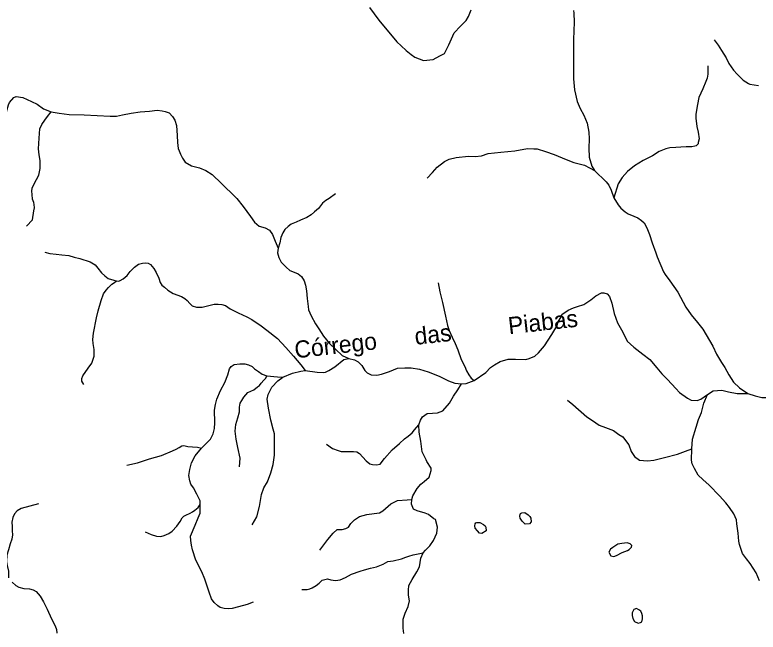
# Model space of a CAD drawing. Extents: x 436.3 to 500.4, y 8231 to 8286.4.
# Drawn here: x 456.96 to 465.65, y 8250.52 to 8257.73 of the extents above; entities that cross this region are included whole.
import ezdxf
from ezdxf.enums import TextEntityAlignment as Align

# ---------------------------------------------------------------- set-up
doc = ezdxf.new("R2010")
doc.units = 0
doc.header["$LTSCALE"] = 0.08
doc.linetypes.add('LONG_DASHED', pattern=[7.5, 6, -1.5])
doc.layers.add('2', color=7, linetype='Continuous', lineweight=25)
doc.layers.add('9', color=7, linetype='LONG_DASHED', lineweight=25)
doc.layers.add('61', color=7, linetype='Continuous')

msp = doc.modelspace()

# ---------------------------------------------------------------- linework, layer by layer
at = {"layer": '2'}
for points in [[(462.8867, 8251.9127), (462.9218, 8251.9161), (462.9637, 8251.8899), (462.9819, 8251.8722), (462.9921, 8251.85), (462.9971, 8251.809), (462.9762, 8251.7844), (462.9269, 8251.7827), (462.8929, 8251.8152), (462.868, 8251.8529), (462.8629, 8251.8745), (462.8668, 8251.8956), (462.8736, 8251.907)], [(462.3636, 8251.8014), (462.3965, 8251.8006), (462.4406, 8251.7786), (462.4588, 8251.7609), (462.4678, 8251.7447), (462.472, 8251.7027), (462.422, 8251.6708), (462.3933, 8251.6778), (462.3698, 8251.7039), (462.3443, 8251.7347), (462.3398, 8251.7632), (462.3437, 8251.7843), (462.3505, 8251.7957)], [(463.9519, 8251.5108), (463.9244, 8251.4907), (463.9045, 8251.4526), (463.927, 8251.4103), (463.962, 8251.4053), (463.9957, 8251.4153), (464.0621, 8251.4506), (464.1221, 8251.4756), (464.1411, 8251.4856), (464.1682, 8251.511), (464.1718, 8251.5339), (464.1555, 8251.5525), (464.1185, 8251.5635), (464.057, 8251.5561), (464.0119, 8251.546)], [(464.2292, 8250.7975), (464.1971, 8250.7855), (464.1771, 8250.7452), (464.1771, 8250.7129), (464.1852, 8250.6807), (464.2053, 8250.6445), (464.2495, 8250.6244), (464.2736, 8250.6324), (464.2896, 8250.6405), (464.2976, 8250.6767), (464.2976, 8250.7089), (464.2894, 8250.7371), (464.2774, 8250.7653), (464.2573, 8250.7815)]]:
    msp.add_lwpolyline(points, close=True, dxfattribs=at)
at = {"layer": '9'}
for points in [[(461.109, 8257.8183), (461.2167, 8257.6723), (461.4273, 8257.4194), (461.4763, 8257.3708), (461.5351, 8257.3173), (461.5939, 8257.2688), (461.6379, 8257.2396), (461.7408, 8257.201), (461.8536, 8257.2111), (461.9319, 8257.2552), (461.9828, 8257.2827), (462.0355, 8257.3819), (462.0991, 8257.5235), (462.1727, 8257.6017), (462.2364, 8257.6653), (462.2658, 8257.7141), (462.2952, 8257.7922)], [(463.4938, 8257.7859), (463.4953, 8257.7547), (463.4987, 8257.6473), (463.4917, 8257.4432), (463.4919, 8256.9858), (463.5025, 8256.8556), (463.5344, 8256.7219), (463.5697, 8256.6374), (463.6127, 8256.5613), (463.6516, 8256.4663), (463.6693, 8256.3641), (463.6763, 8256.283), (463.6727, 8256.1737), (463.6762, 8256.0714), (463.7081, 8255.9655), (463.7362, 8255.9162)], [(465.1344, 8257.4415), (465.1818, 8257.3782), (465.22, 8257.3181), (465.274, 8257.2326), (465.3089, 8257.163), (465.3628, 8257.0869), (465.4041, 8257.0395), (465.4739, 8256.9697), (465.5373, 8256.9316), (465.5532, 8256.9221), (465.6546, 8256.9093)], [(465.0626, 8257.1391), (465.0626, 8257.1051), (465.0626, 8257.0404), (465.0524, 8256.9929), (465.0388, 8256.9554), (465.0048, 8256.867), (464.9571, 8256.7683), (464.94, 8256.6866), (464.9196, 8256.5709), (464.9196, 8256.5267), (464.9333, 8256.4279), (464.9504, 8256.3632), (464.9606, 8256.2847), (464.9504, 8256.2405), (464.9469, 8256.2269), (464.9262, 8256.2043), (464.9091, 8256.1975), (464.8751, 8256.1908), (464.8103, 8256.1909), (464.7455, 8256.1875), (464.6875, 8256.1841), (464.6193, 8256.1773), (464.5715, 8256.1672), (464.4931, 8256.1366), (464.4146, 8256.0854), (464.3055, 8256.031), (464.2031, 8255.9696), (464.1245, 8255.9013), (464.0597, 8255.833), (464.0153, 8255.7579), (463.9628, 8255.5963)], [(456.8411, 8256.1236), (456.845, 8256.2545), (456.8451, 8256.3369), (456.8526, 8256.4304), (456.8527, 8256.5014), (456.8678, 8256.5987), (456.8903, 8256.6809), (456.9016, 8256.7108), (456.9541, 8256.7668), (456.9802, 8256.778), (457.059, 8256.7667), (457.16, 8256.7218), (457.2236, 8256.6881), (457.2984, 8256.6357), (457.389, 8256.5984)], [(457.1018, 8255.2657), (457.1686, 8255.3385), (457.1869, 8255.4415), (457.1925, 8255.4767), (457.189, 8255.5154), (457.1855, 8255.5401), (457.1715, 8255.5788), (457.1646, 8255.6352), (457.161, 8255.6739), (457.1647, 8255.7091), (457.1929, 8255.7655), (457.2176, 8255.8076), (457.2459, 8255.8604), (457.2601, 8255.9379), (457.2602, 8256.0329), (457.2497, 8256.0963), (457.2392, 8256.1666), (457.25, 8256.2933), (457.257, 8256.4002), (457.2782, 8256.4529), (457.3135, 8256.5022), (457.3453, 8256.5444), (457.389, 8256.5984)], [(457.389, 8256.5984), (457.4826, 8256.5833), (457.5986, 8256.5683), (457.7746, 8256.5645), (457.9244, 8256.5569), (458.0787, 8256.5495), (458.1536, 8256.5494), (458.221, 8256.5644), (458.3222, 8256.583), (458.4271, 8256.598), (458.5394, 8256.6092), (458.6256, 8256.6205), (458.6855, 8256.613), (458.7192, 8256.6055), (458.7678, 8256.5869), (458.8052, 8256.5457), (458.8352, 8256.5009), (458.8539, 8256.4411), (458.8611, 8256.3252), (458.8648, 8256.243), (458.873, 8256.1707), (458.8842, 8256.1445), (458.8992, 8256.1034), (458.9215, 8256.0585), (458.9552, 8256.0099), (459.03, 8255.9688), (459.1199, 8255.9465), (459.1948, 8255.9129), (459.2696, 8255.8681), (459.3781, 8255.7633), (459.4267, 8255.7148), (459.4954, 8255.6489), (459.559, 8255.5854), (459.6312, 8255.4924), (459.6747, 8255.4359), (459.716, 8255.376), (459.7649, 8255.3097), (459.8193, 8255.2641), (459.8881, 8255.2452), (459.9393, 8255.2174), (459.9741, 8255.1669), (460.0043, 8255.0872), (460.0416, 8255.0085)], [(461.7839, 8255.8256), (461.8436, 8255.8898), (461.8988, 8255.954), (461.9859, 8256.0183), (462.041, 8256.046), (462.119, 8256.0645), (462.2659, 8256.0833), (462.3437, 8256.079), (462.4172, 8256.0838), (462.4952, 8256.1114), (462.6419, 8256.1302), (462.8071, 8256.1445), (462.9538, 8256.1724), (463.0272, 8256.1681), (463.0684, 8256.1682), (463.1648, 8256.1364), (463.2656, 8256.1001), (463.4077, 8256.041), (463.4953, 8256.0091), (463.619, 8255.9773), (463.7362, 8255.9162)], [(463.7362, 8255.9162), (463.8741, 8255.7821), (463.9063, 8255.7413), (463.931, 8255.6847), (463.9628, 8255.5963)], [(460.7109, 8255.641), (460.6374, 8255.5859), (460.5971, 8255.5639), (460.5603, 8255.5309), (460.5126, 8255.4722), (460.4648, 8255.4318), (460.4281, 8255.3951), (460.3767, 8255.3657), (460.3033, 8255.3327), (460.2519, 8255.3106), (460.1932, 8255.2885), (460.1565, 8255.2592), (460.1198, 8255.2261), (460.094, 8255.1858), (460.0719, 8255.1308), (460.0609, 8255.0686), (460.0416, 8255.0085)], [(463.9628, 8255.5963), (464.0121, 8255.515), (464.0439, 8255.4761), (464.097, 8255.4301), (464.1322, 8255.4089), (464.1958, 8255.3807), (464.2453, 8255.3594), (464.2876, 8255.3311), (464.3159, 8255.3028), (464.3476, 8255.2426), (464.3793, 8255.1648), (464.411, 8255.0691), (464.4533, 8254.9523), (464.4678, 8254.9072), (464.5453, 8254.7301), (464.5629, 8254.6982), (464.6194, 8254.6237), (464.7112, 8254.4926), (464.8064, 8254.3188), (464.8664, 8254.2267), (464.9405, 8254.1379), (465.004, 8254.0598), (465.1189, 8253.8623), (465.1612, 8253.77), (465.2212, 8253.6707), (465.26, 8253.6139), (465.3059, 8253.5252), (465.3623, 8253.44), (465.4329, 8253.3761), (465.5283, 8253.3087)], [(460.0416, 8255.0085), (460.0349, 8254.9512), (460.0495, 8254.8963), (460.075, 8254.8451), (460.1336, 8254.7828), (460.1782, 8254.7444), (460.2295, 8254.7261), (460.2735, 8254.7079), (460.3137, 8254.6749), (460.343, 8254.6237), (460.3612, 8254.576), (460.3721, 8254.51), (460.3792, 8254.4183), (460.39, 8254.3267), (460.3972, 8254.2863), (460.4265, 8254.2167), (460.4777, 8254.1214), (460.5179, 8254.0627), (460.5688, 8253.9802), (460.642, 8253.8922), (460.7153, 8253.8225), (460.7885, 8253.7529), (460.867, 8253.7176)], [(457.3139, 8254.9613), (457.3745, 8254.9429), (457.4482, 8254.935), (457.5141, 8254.927), (457.5958, 8254.9217), (457.6564, 8254.9032), (457.7249, 8254.8874), (457.8434, 8254.8478), (457.9013, 8254.8135), (457.9329, 8254.774), (457.9775, 8254.7185), (458.017, 8254.6816), (458.0539, 8254.6526), (458.1197, 8254.6315), (458.1523, 8254.6256)], [(458.1523, 8254.6256), (458.1787, 8254.6229), (458.1945, 8254.6283), (458.2288, 8254.6467), (458.2763, 8254.6863), (458.3133, 8254.7338), (458.3635, 8254.7865), (458.4083, 8254.8209), (458.4558, 8254.8314), (458.4901, 8254.8367), (458.5217, 8254.8314), (458.5507, 8254.8156), (458.5875, 8254.7682), (458.6164, 8254.7207), (458.6479, 8254.6547), (458.6636, 8254.6073), (458.682, 8254.5729), (458.711, 8254.5492), (458.7531, 8254.515), (458.8136, 8254.4754), (458.9111, 8254.4412), (458.9519, 8254.4191), (458.9782, 8254.3953), (459.0097, 8254.3583), (459.036, 8254.3346), (459.0862, 8254.3188), (459.152, 8254.3163), (459.2153, 8254.3348), (459.2919, 8254.3506), (459.3394, 8254.3507), (459.3842, 8254.3481), (459.4237, 8254.3349), (459.479, 8254.298), (459.5739, 8254.2506), (459.6741, 8254.2059), (459.7336, 8254.1734), (459.8442, 8254.0995), (459.9101, 8254.0467), (460.0314, 8253.9519), (460.1314, 8253.8462), (460.2209, 8253.746), (460.3052, 8253.643), (460.3579, 8253.577)], [(457.77, 8253.4134), (457.7483, 8253.4514), (457.7484, 8253.4841), (457.7593, 8253.5168), (457.8192, 8253.6038), (457.8627, 8253.6637), (457.89, 8253.7453), (457.8901, 8253.8214), (457.8794, 8253.8921), (457.874, 8253.9411), (457.885, 8254.0118), (457.9179, 8254.1913), (457.9388, 8254.2756), (457.9716, 8254.3952), (457.9989, 8254.4713), (458.0316, 8254.5148), (458.0588, 8254.5473), (458.0969, 8254.5854), (458.1295, 8254.6072), (458.1523, 8254.6256)], [(461.9106, 8254.603), (461.9289, 8254.4975), (461.9607, 8254.3737), (461.9972, 8254.2131), (462.0199, 8254.1036), (462.0383, 8254.0452), (462.0754, 8253.9657), (462.1098, 8253.894), (462.1416, 8253.8169), (462.1812, 8253.7068), (462.221, 8253.6245), (462.2421, 8253.5714), (462.2686, 8253.5262), (462.2951, 8253.489), (462.3296, 8253.4598)], [(462.3296, 8253.4598), (462.4677, 8253.553), (462.5235, 8253.6116), (462.5694, 8253.6441), (462.6348, 8253.6825), (462.7275, 8253.7098), (462.8147, 8253.71), (462.9368, 8253.7075), (462.975, 8253.7185), (463.0404, 8253.7458), (463.0841, 8253.7841), (463.155, 8253.8661), (463.2369, 8253.9973), (463.2969, 8254.0956), (463.3134, 8254.1448), (463.3461, 8254.2049), (463.357, 8254.2322), (463.4278, 8254.2815), (463.4933, 8254.3088), (463.5369, 8254.3252), (463.6131, 8254.3471), (463.6949, 8254.4019), (463.7548, 8254.451), (463.8202, 8254.4838), (463.8474, 8254.4838), (463.8855, 8254.4729), (463.9127, 8254.4402), (463.9398, 8254.3638), (463.9669, 8254.2437), (464.0049, 8254.1345), (464.0702, 8254.0253), (464.1191, 8253.9215), (464.1953, 8253.8505), (464.3012, 8253.7666), (464.3828, 8253.7065), (464.4644, 8253.6082), (464.5242, 8253.5371), (464.5895, 8253.4716), (464.6874, 8253.3677), (464.7309, 8253.3185), (464.8235, 8253.2529), (464.8669, 8253.2311), (464.9377, 8253.2256), (464.9812, 8253.2419), (465.0574, 8253.2966)], [(460.3579, 8253.577), (460.4962, 8253.559), (460.567, 8253.5537), (460.5942, 8253.5591), (460.6324, 8253.5755), (460.7033, 8253.6192), (460.807, 8253.7066), (460.867, 8253.7176)], [(460.867, 8253.7176), (460.9324, 8253.7012), (460.9759, 8253.6795), (461.0194, 8253.636), (461.052, 8253.576), (461.0792, 8253.5488), (461.1282, 8253.5271), (461.1936, 8253.5217), (461.2481, 8253.5326), (461.3426, 8253.5661), (461.4353, 8253.6044), (461.5225, 8253.61), (461.5934, 8253.6101), (461.6915, 8253.5938), (461.795, 8253.5613), (461.9204, 8253.5122), (462.0294, 8253.4579), (462.1057, 8253.4306), (462.1821, 8253.4198)], [(459.1449, 8252.6713), (459.2507, 8252.7763), (459.2805, 8252.8377), (459.2955, 8252.9005), (459.3016, 8252.9662), (459.3017, 8253.0199), (459.2988, 8253.0618), (459.2989, 8253.1156), (459.308, 8253.1784), (459.323, 8253.241), (459.3678, 8253.3427), (459.4189, 8253.4369), (459.4519, 8253.5265), (459.4729, 8253.5953), (459.4909, 8253.6251), (459.5267, 8253.646), (459.5923, 8253.6551), (459.652, 8253.6551), (459.6937, 8253.6431), (459.7384, 8253.6223), (459.7652, 8253.5955), (459.8129, 8253.5657), (459.8546, 8253.5358), (459.9095, 8253.5145)], [(459.5885, 8252.4512), (459.5956, 8252.5524), (459.5714, 8252.6782), (459.5507, 8252.7759), (459.5368, 8252.8666), (459.5474, 8252.947), (459.5685, 8253.0238), (459.5902, 8253.0941), (459.5903, 8253.1507), (459.5987, 8253.1958), (459.6176, 8253.2263), (459.6404, 8253.2658), (459.6875, 8253.3205), (459.7572, 8253.352), (459.8012, 8253.3848), (459.8243, 8253.4017), (459.8439, 8253.4274), (459.8724, 8253.4631), (459.8955, 8253.4879), (459.9095, 8253.5145)], [(459.736, 8251.7746), (459.7903, 8251.8673), (459.823, 8251.9872), (459.8447, 8252.1291), (459.8719, 8252.2054), (459.9156, 8252.2763), (459.9538, 8252.3799), (459.9811, 8252.4781), (459.9976, 8252.5872), (459.9979, 8252.838), (459.9817, 8252.8925), (459.9547, 8252.9961), (459.9277, 8253.1378), (459.9115, 8253.2414), (459.9232, 8253.2965), (459.9669, 8253.3837), (460.0378, 8253.4546), (460.0974, 8253.4997)], [(459.9095, 8253.5145), (460.0348, 8253.5027), (460.0974, 8253.4997)], [(460.0974, 8253.4997), (460.2075, 8253.5478), (460.3056, 8253.5697), (460.3579, 8253.577)], [(461.6843, 8252.9404), (461.7028, 8252.9957), (461.7259, 8253.0373), (461.7813, 8253.0743), (461.8459, 8253.079), (461.9012, 8253.0837), (461.9658, 8253.1068), (462.0443, 8253.1946), (462.0904, 8253.2777), (462.1412, 8253.3517), (462.1821, 8253.4198)], [(462.1821, 8253.4198), (462.2367, 8253.4252), (462.3296, 8253.4598)], [(465.0574, 8253.2966), (465.1227, 8253.3403), (465.226, 8253.3457), (465.3021, 8253.3293), (465.4055, 8253.3075), (465.5283, 8253.3087)], [(464.8737, 8252.6621), (464.8841, 8252.7761), (464.9235, 8252.9169), (464.9542, 8253.0049), (464.9887, 8253.0873), (465.0048, 8253.1503), (465.0156, 8253.1952), (465.0574, 8253.2966)], [(465.5283, 8253.3087), (465.6131, 8253.2803), (465.6913, 8253.2631), (465.7649, 8253.2625), (465.846, 8253.2944)], [(463.4229, 8253.2293), (463.4843, 8253.181), (463.6465, 8253.0359), (463.7123, 8252.9919), (463.7912, 8252.9391), (463.8657, 8252.9127), (463.9578, 8252.8775), (464.0236, 8252.8292), (464.0674, 8252.8028), (464.098, 8252.7588), (464.1376, 8252.7104), (464.1639, 8252.6312), (464.2033, 8252.574), (464.2646, 8252.53), (464.3567, 8252.5212), (464.4312, 8252.53), (464.5539, 8252.5609), (464.7072, 8252.6004), (464.7992, 8252.6356), (464.8737, 8252.6621)], [(460.6047, 8252.7177), (460.6739, 8252.6671), (460.743, 8252.6441), (460.7752, 8252.6302), (460.8121, 8252.6302), (460.8721, 8252.6303), (460.9228, 8252.6303), (460.9596, 8252.6257), (460.9919, 8252.6073), (461.0287, 8252.5657), (461.0702, 8252.5197), (461.1117, 8252.4874), (461.144, 8252.4781), (461.1901, 8252.4735), (461.2316, 8252.4828), (461.2823, 8252.5474), (461.3747, 8252.649), (461.4591, 8252.7246), (461.5185, 8252.7781), (461.5593, 8252.8107), (461.6054, 8252.8476), (461.6331, 8252.8846), (461.6843, 8252.9404)], [(461.6012, 8252.0707), (461.615, 8252.112), (461.6657, 8252.1998), (461.7072, 8252.2505), (461.7487, 8252.2782), (461.804, 8252.3291), (461.8272, 8252.4075), (461.8272, 8252.4353), (461.7764, 8252.5137), (461.7718, 8252.5322), (461.7255, 8252.6265), (461.7072, 8252.7511), (461.6888, 8252.8572), (461.6843, 8252.9404)], [(458.274, 8252.4713), (458.3975, 8252.4995), (458.5378, 8252.5445), (458.6782, 8252.584), (458.8073, 8252.6403), (458.8479, 8252.6579), (458.8827, 8252.6784), (458.9144, 8252.6958), (458.94, 8252.6989), (458.9861, 8252.6894), (459.0385, 8252.684), (459.0999, 8252.6804), (459.1449, 8252.6713)], [(459.1308, 8252.0112), (459.1308, 8252.053), (459.0922, 8252.1338), (459.0505, 8252.2055), (459.0207, 8252.2503), (459.0088, 8252.2861), (458.9969, 8252.3489), (459.0089, 8252.4206), (459.0268, 8252.4983), (459.0716, 8252.5789), (459.1449, 8252.6713)], [(465.6655, 8251.1187), (465.6261, 8251.211), (465.5559, 8251.3208), (465.5121, 8251.378), (465.4683, 8251.4396), (465.4331, 8251.5451), (465.4244, 8251.5847), (465.4155, 8251.6771), (465.4024, 8251.7871), (465.3979, 8251.8311), (465.3672, 8251.9015), (465.3146, 8251.9763), (465.2708, 8252.029), (465.1964, 8252.1126), (465.077, 8252.2382), (465.0025, 8252.3043), (464.95, 8252.3527), (464.9061, 8252.4319), (464.8798, 8252.4857), (464.8709, 8252.5296), (464.8737, 8252.6621)], [(460.5273, 8251.4758), (460.6221, 8251.6008), (460.6821, 8251.6758), (460.7319, 8251.7209), (460.787, 8251.7208), (460.8319, 8251.7308), (460.8619, 8251.7458), (460.8919, 8251.7908), (460.9319, 8251.8309), (460.9918, 8251.8708), (461.0768, 8251.8958), (461.1618, 8251.9059), (461.2268, 8251.9159), (461.2633, 8251.937), (461.3576, 8252.0205), (461.4343, 8252.0578), (461.5495, 8252.0663), (461.6012, 8252.0707)], [(461.7353, 8251.4472), (461.7629, 8251.4795), (461.8136, 8251.5302), (461.8551, 8251.5903), (461.8965, 8251.678), (461.9011, 8251.7473), (461.878, 8251.835), (461.8595, 8251.8442), (461.7995, 8251.895), (461.758, 8251.9089), (461.6657, 8251.9365), (461.6242, 8251.955), (461.5983, 8252.0151), (461.6012, 8252.0707)], [(457.241, 8252.0191), (457.1408, 8251.9925), (457.0374, 8251.9629), (456.9902, 8251.9362), (456.9608, 8251.9007), (456.9401, 8251.8593), (456.9283, 8251.806), (456.9312, 8251.7527), (456.9342, 8251.7054), (456.9371, 8251.658), (456.9284, 8251.6047), (456.9106, 8251.5515), (456.89, 8251.4834), (456.8694, 8251.4182), (456.8665, 8251.3442), (456.8754, 8251.2998), (456.8901, 8251.2317), (456.8904, 8251.1529)], [(458.4883, 8251.6926), (458.5582, 8251.6605), (458.6194, 8251.6429), (458.669, 8251.6371), (458.7097, 8251.6488), (458.7621, 8251.6721), (458.8029, 8251.6985), (458.8582, 8251.7569), (458.8961, 8251.8124), (458.9193, 8251.8563), (458.9368, 8251.8738), (458.9631, 8251.8854), (459.0126, 8251.9088), (459.0417, 8251.9264), (459.0679, 8251.9468), (459.1058, 8251.9761), (459.1308, 8252.0112)], [(459.7496, 8250.8711), (459.6781, 8250.8443), (459.5768, 8250.8144), (459.5022, 8250.7965), (459.4604, 8250.7906), (459.4097, 8250.7965), (459.362, 8250.8085), (459.3351, 8250.8264), (459.2934, 8250.8654), (459.2634, 8250.9072), (459.2335, 8250.9878), (459.1823, 8251.1392), (459.1494, 8251.2259), (459.0807, 8251.3603), (459.0389, 8251.4799), (459.0269, 8251.5366), (459.0209, 8251.5889), (459.0179, 8251.6427), (459.0714, 8251.7682), (459.1042, 8251.8549), (459.1279, 8251.9096), (459.1308, 8251.9484), (459.1308, 8252.0112)], [(460.3182, 8251.0189), (460.3781, 8251.0188), (460.411, 8251.0248), (460.4369, 8251.0379), (460.4836, 8251.0663), (460.5199, 8251.0923), (460.5561, 8251.126), (460.5872, 8251.1363), (460.6157, 8251.1415), (460.6546, 8251.1312), (460.7117, 8251.1233), (460.7636, 8251.1311), (460.8284, 8251.1596), (460.8984, 8251.1959), (460.9973, 8251.2331), (461.0492, 8251.2486), (461.1218, 8251.2668), (461.1894, 8251.2823), (461.2697, 8251.316), (461.3242, 8251.3446), (461.3839, 8251.3524), (461.4825, 8251.3757), (461.5344, 8251.3964), (461.5682, 8251.4095), (461.6175, 8251.4224), (461.7353, 8251.4472)], [(461.5106, 8250.5024), (461.5012, 8250.567), (461.501, 8250.6731), (461.5239, 8250.7423), (461.5608, 8250.8207), (461.5745, 8250.8853), (461.5651, 8250.9507), (461.565, 8251.0107), (461.5695, 8251.0662), (461.6063, 8251.1353), (461.6615, 8251.223), (461.6938, 8251.283), (461.7076, 8251.3845), (461.7353, 8251.4472)], [(456.9317, 8251.1041), (456.9744, 8251.0664), (457.0109, 8251.0469), (457.0693, 8251.0298), (457.1349, 8251.025), (457.1787, 8251.0151), (457.2128, 8250.9932), (457.259, 8250.9395), (457.3004, 8250.8737), (457.3419, 8250.7884), (457.3931, 8250.6761), (457.4345, 8250.5932), (457.4517, 8250.5523), (457.4541, 8250.5084)]]:
    msp.add_lwpolyline(points, dxfattribs=at)

# ---------------------------------------------------------------- texts
at = {"layer": '61'}
msp.add_text('Córrego      das         Piabas', height=0.2, rotation=6.41, dxfattribs=at).set_placement((461.8974, 8253.9045), align=Align.CENTER)

doc.saveas('drawing.dxf')
